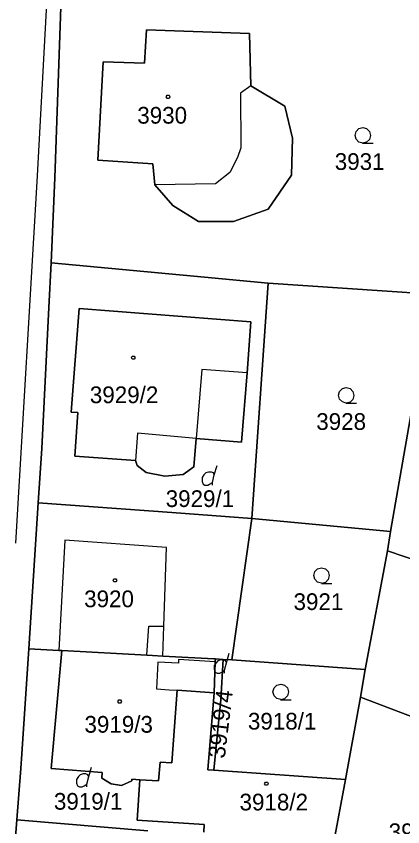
# Model space of a CAD drawing. Extents: x -263587 to -261993, y -1238795 to -1236748.
# Drawn here: x -262927.6 to -262890.6, y -1238078.5 to -1238000.9 of the extents above; entities that cross this region are included whole.
import ezdxf

# ---------------------------------------------------------------- set-up
doc = ezdxf.new("R2010")
doc.units = 0
doc.layers.add('Vrstva 1', color=7, linetype='Continuous')

msp = doc.modelspace()

# ---------------------------------------------------------------- linework, layer by layer
at = {"layer": 'Vrstva 1'}
for p, q in [((-262924.5, -1237996.8), (-262925.57, -1238016.17)), ((-262923.19, -1237996.8), (-262923.88, -1238016.37)), ((-262923.88, -1238016.37), (-262923.19, -1237996.8)), ((-262915.12, -1238002.2), (-262915.29, -1238005.41)), ((-262915.29, -1238005.41), (-262915.12, -1238002.2)), ((-262905.25, -1238002.56), (-262915.12, -1238002.2)), ((-262915.12, -1238002.2), (-262905.25, -1238002.56)), ((-262905.14, -1238007.57), (-262905.25, -1238002.56)), ((-262905.25, -1238002.56), (-262905.14, -1238007.57)), ((-262919.25, -1238005.29), (-262919.76, -1238014.67)), ((-262919.76, -1238014.67), (-262919.25, -1238005.29)), ((-262915.29, -1238005.41), (-262919.25, -1238005.29)), ((-262919.25, -1238005.29), (-262915.29, -1238005.41)), ((-262905.14, -1238007.57), (-262906.13, -1238008.26)), ((-262901.89, -1238009.51), (-262905.14, -1238007.57)), ((-262905.14, -1238007.57), (-262901.89, -1238009.51)), ((-262906.13, -1238008.26), (-262906.11, -1238013.5)), ((-262901.14, -1238012.57), (-262901.89, -1238009.51)), ((-262901.89, -1238009.51), (-262901.14, -1238012.57)), ((-262901.24, -1238016.12), (-262901.14, -1238012.57)), ((-262901.14, -1238012.57), (-262901.24, -1238016.12)), ((-262906.11, -1238013.5), (-262906.41, -1238014.44)), ((-262906.41, -1238014.44), (-262907.15, -1238015.86)), ((-262919.76, -1238014.67), (-262914.51, -1238015.05)), ((-262914.51, -1238015.05), (-262919.76, -1238014.67)), ((-262914.51, -1238015.05), (-262914.33, -1238017.04)), ((-262914.33, -1238017.04), (-262914.51, -1238015.05)), ((-262907.15, -1238015.86), (-262908.52, -1238016.95)), ((-262925.57, -1238016.17), (-262927.63, -1238051.34)), ((-262923.88, -1238016.37), (-262924.22, -1238024.51)), ((-262924.22, -1238024.51), (-262923.88, -1238016.37)), ((-262903.47, -1238019.38), (-262901.24, -1238016.12)), ((-262901.24, -1238016.12), (-262903.47, -1238019.38)), ((-262908.52, -1238016.95), (-262914.33, -1238017.04)), ((-262914.33, -1238017.04), (-262912.6, -1238019.01)), ((-262912.6, -1238019.01), (-262914.33, -1238017.04)), ((-262912.6, -1238019.01), (-262910.15, -1238020.57)), ((-262910.15, -1238020.57), (-262912.6, -1238019.01)), ((-262906.79, -1238020.57), (-262903.47, -1238019.38)), ((-262903.47, -1238019.38), (-262906.79, -1238020.57)), ((-262910.15, -1238020.57), (-262906.79, -1238020.57)), ((-262906.79, -1238020.57), (-262910.15, -1238020.57)), ((-262924.22, -1238024.51), (-262924.44, -1238028.79)), ((-262924.44, -1238028.79), (-262924.22, -1238024.51)), ((-262909.56, -1238025.88), (-262924.22, -1238024.51)), ((-262924.22, -1238024.51), (-262909.56, -1238025.88)), ((-262903.47, -1238026.45), (-262909.56, -1238025.88)), ((-262909.56, -1238025.88), (-262903.47, -1238026.45)), ((-262905.05, -1238048.98), (-262903.47, -1238026.45)), ((-262903.47, -1238026.45), (-262905.05, -1238048.98)), ((-262903.47, -1238026.45), (-262887.93, -1238027.52)), ((-262887.93, -1238027.52), (-262903.47, -1238026.45)), ((-262924.44, -1238028.79), (-262925.12, -1238042.27)), ((-262925.12, -1238042.27), (-262924.44, -1238028.79)), ((-262922.32, -1238038.79), (-262921.56, -1238028.88)), ((-262921.56, -1238028.88), (-262922.32, -1238038.79)), ((-262921.56, -1238028.88), (-262905.13, -1238030.16)), ((-262905.13, -1238030.16), (-262921.56, -1238028.88)), ((-262905.13, -1238030.16), (-262905.49, -1238035.03)), ((-262905.49, -1238035.03), (-262905.13, -1238030.16)), ((-262909.81, -1238034.73), (-262910.37, -1238041.32)), ((-262905.49, -1238035.03), (-262909.81, -1238034.73)), ((-262905.49, -1238035.03), (-262906.03, -1238041.69)), ((-262906.03, -1238041.69), (-262905.49, -1238035.03)), ((-262921.67, -1238038.82), (-262922.32, -1238038.79)), ((-262922.32, -1238038.79), (-262921.67, -1238038.82)), ((-262921.97, -1238043.01), (-262921.67, -1238038.82)), ((-262921.67, -1238038.82), (-262921.97, -1238043.01)), ((-262891.79, -1238050.23), (-262889.81, -1238038.9)), ((-262889.81, -1238038.9), (-262891.79, -1238050.23)), ((-262915.98, -1238040.82), (-262916.15, -1238043.42)), ((-262910.37, -1238041.32), (-262915.98, -1238040.82)), ((-262910.37, -1238041.32), (-262910.59, -1238044.05)), ((-262910.59, -1238044.05), (-262910.37, -1238041.32)), ((-262906.03, -1238041.69), (-262910.37, -1238041.32)), ((-262910.37, -1238041.32), (-262906.03, -1238041.69)), ((-262925.12, -1238042.27), (-262925.48, -1238047.47)), ((-262925.48, -1238047.47), (-262925.12, -1238042.27)), ((-262916.15, -1238043.42), (-262921.97, -1238043.01)), ((-262921.97, -1238043.01), (-262916.15, -1238043.42)), ((-262915.99, -1238043.9), (-262916.15, -1238043.42)), ((-262916.15, -1238043.42), (-262915.99, -1238043.9)), ((-262915.14, -1238044.57), (-262915.99, -1238043.9)), ((-262915.99, -1238043.9), (-262915.14, -1238044.57)), ((-262908.63, -1238044.8), (-262908.36, -1238043.9)), ((-262913.37, -1238044.93), (-262915.14, -1238044.57)), ((-262915.14, -1238044.57), (-262913.37, -1238044.93)), ((-262910.59, -1238044.05), (-262911.61, -1238044.78)), ((-262911.61, -1238044.78), (-262910.59, -1238044.05)), ((-262911.61, -1238044.78), (-262913.37, -1238044.93)), ((-262913.37, -1238044.93), (-262911.61, -1238044.78)), ((-262926.37, -1238061.45), (-262925.48, -1238047.47)), ((-262925.48, -1238047.47), (-262926.37, -1238061.45)), ((-262925.48, -1238047.47), (-262912.7, -1238048.41)), ((-262912.7, -1238048.41), (-262925.48, -1238047.47)), ((-262912.7, -1238048.41), (-262905.05, -1238048.98)), ((-262905.05, -1238048.98), (-262912.7, -1238048.41)), ((-262906.97, -1238062.51), (-262905.05, -1238048.98)), ((-262905.05, -1238048.98), (-262906.97, -1238062.51)), ((-262891.79, -1238050.23), (-262905.05, -1238048.98)), ((-262905.05, -1238048.98), (-262891.79, -1238050.23)), ((-262892.07, -1238052.07), (-262891.79, -1238050.23)), ((-262891.79, -1238050.23), (-262892.07, -1238052.07)), ((-262922.91, -1238051.04), (-262923.48, -1238061.61)), ((-262913.2, -1238051.74), (-262922.91, -1238051.04)), ((-262913.47, -1238059.3), (-262913.2, -1238051.74)), ((-262894.2, -1238063.43), (-262892.07, -1238052.07)), ((-262892.07, -1238052.07), (-262894.2, -1238063.43)), ((-262892.07, -1238052.07), (-262876.57, -1238057.4)), ((-262876.57, -1238057.4), (-262892.07, -1238052.07)), ((-262915.07, -1238062.06), (-262914.9, -1238059.29)), ((-262914.9, -1238059.29), (-262913.47, -1238059.3)), ((-262913.55, -1238062.15), (-262913.47, -1238059.3)), ((-262926.37, -1238061.45), (-262927.02, -1238071.5)), ((-262927.02, -1238071.5), (-262926.37, -1238061.45)), ((-262923.48, -1238061.61), (-262926.37, -1238061.45)), ((-262926.37, -1238061.45), (-262923.48, -1238061.61)), ((-262923.22, -1238061.62), (-262924.23, -1238072.91)), ((-262924.23, -1238072.91), (-262923.22, -1238061.62)), ((-262923.22, -1238061.62), (-262923.48, -1238061.61)), ((-262923.48, -1238061.61), (-262923.22, -1238061.62)), ((-262915.07, -1238062.06), (-262923.22, -1238061.62)), ((-262923.22, -1238061.62), (-262915.07, -1238062.06)), ((-262914.54, -1238062.09), (-262915.07, -1238062.06)), ((-262915.07, -1238062.06), (-262914.54, -1238062.09)), ((-262913.55, -1238062.15), (-262914.54, -1238062.09)), ((-262914.54, -1238062.09), (-262913.55, -1238062.15)), ((-262908.67, -1238062.4), (-262913.55, -1238062.15)), ((-262913.55, -1238062.15), (-262908.67, -1238062.4)), ((-262912.04, -1238062.48), (-262912.06, -1238062.83)), ((-262908.54, -1238062.69), (-262912.04, -1238062.48)), ((-262908.53, -1238062.41), (-262908.67, -1238062.4)), ((-262908.67, -1238062.4), (-262908.53, -1238062.41)), ((-262908.53, -1238062.41), (-262908.54, -1238062.69)), ((-262908.54, -1238062.69), (-262908.53, -1238062.41)), ((-262907.77, -1238062.46), (-262908.53, -1238062.41)), ((-262908.53, -1238062.41), (-262907.77, -1238062.46)), ((-262908.01, -1238066.3), (-262907.77, -1238062.46)), ((-262907.77, -1238062.46), (-262908.01, -1238066.3)), ((-262906.97, -1238062.51), (-262907.77, -1238062.46)), ((-262907.77, -1238062.46), (-262906.97, -1238062.51)), ((-262907.47, -1238062.78), (-262907.2, -1238061.88)), ((-262894.2, -1238063.43), (-262906.97, -1238062.51)), ((-262906.97, -1238062.51), (-262894.2, -1238063.43)), ((-262914.03, -1238062.73), (-262914.17, -1238065.27)), ((-262912.06, -1238062.83), (-262914.03, -1238062.73)), ((-262908.54, -1238062.69), (-262908.65, -1238065.68)), ((-262908.65, -1238065.68), (-262908.54, -1238062.69)), ((-262894.64, -1238066.09), (-262894.2, -1238063.43)), ((-262894.2, -1238063.43), (-262894.64, -1238066.09)), ((-262914.17, -1238065.27), (-262912.96, -1238065.37)), ((-262912.96, -1238065.37), (-262912.19, -1238065.42)), ((-262912.69, -1238072.37), (-262912.19, -1238065.42)), ((-262912.19, -1238065.42), (-262912.69, -1238072.37)), ((-262912.19, -1238065.42), (-262908.65, -1238065.68)), ((-262908.65, -1238065.68), (-262912.19, -1238065.42)), ((-262908.65, -1238065.68), (-262909.26, -1238073.03)), ((-262909.26, -1238073.03), (-262908.65, -1238065.68)), ((-262908.67, -1238073.06), (-262908.01, -1238066.3)), ((-262908.01, -1238066.3), (-262908.67, -1238073.06)), ((-262896.1, -1238073.96), (-262894.64, -1238066.09)), ((-262894.64, -1238066.09), (-262896.1, -1238073.96)), ((-262894.64, -1238066.09), (-262880.22, -1238071.61)), ((-262880.22, -1238071.61), (-262894.64, -1238066.09)), ((-262927.02, -1238071.5), (-262927.11, -1238072.91)), ((-262927.11, -1238072.91), (-262927.02, -1238071.5)), ((-262913.95, -1238074.08), (-262913.82, -1238072.29)), ((-262913.82, -1238072.29), (-262913.95, -1238074.08)), ((-262913.82, -1238072.29), (-262912.69, -1238072.37)), ((-262912.69, -1238072.37), (-262913.82, -1238072.29)), ((-262927.11, -1238072.91), (-262927.5, -1238077.82)), ((-262927.5, -1238077.82), (-262927.11, -1238072.91)), ((-262924.23, -1238072.91), (-262919.35, -1238073.29)), ((-262919.35, -1238073.29), (-262924.23, -1238072.91)), ((-262920.63, -1238073.68), (-262920.36, -1238072.78)), ((-262919.35, -1238073.29), (-262919.39, -1238073.84)), ((-262919.39, -1238073.84), (-262919.35, -1238073.29)), ((-262909.26, -1238073.03), (-262908.67, -1238073.06)), ((-262908.67, -1238073.06), (-262909.26, -1238073.03)), ((-262896.1, -1238073.96), (-262908.67, -1238073.06)), ((-262908.67, -1238073.06), (-262896.1, -1238073.96)), ((-262919.39, -1238073.84), (-262918.48, -1238074.38)), ((-262918.48, -1238074.38), (-262919.39, -1238073.84)), ((-262917.5, -1238074.53), (-262916.51, -1238074.1)), ((-262916.51, -1238074.1), (-262917.5, -1238074.53)), ((-262916.51, -1238074.1), (-262916.5, -1238073.94)), ((-262916.5, -1238073.94), (-262916.51, -1238074.1)), ((-262916.5, -1238073.94), (-262915.74, -1238073.99)), ((-262915.74, -1238073.99), (-262916.5, -1238073.94)), ((-262916.01, -1238077.84), (-262915.74, -1238073.99)), ((-262915.74, -1238073.99), (-262916.01, -1238077.84)), ((-262915.74, -1238073.99), (-262913.95, -1238074.08)), ((-262913.95, -1238074.08), (-262915.74, -1238073.99)), ((-262897.27, -1238080.27), (-262896.1, -1238073.96)), ((-262896.1, -1238073.96), (-262897.27, -1238080.27)), ((-262918.48, -1238074.38), (-262917.5, -1238074.53)), ((-262917.5, -1238074.53), (-262918.48, -1238074.38)), ((-262928.43, -1238089.35), (-262927.5, -1238077.82)), ((-262927.5, -1238077.82), (-262928.43, -1238089.35)), ((-262927.5, -1238077.82), (-262915, -1238078.87)), ((-262915, -1238078.87), (-262927.5, -1238077.82)), ((-262909.6, -1238078.28), (-262916.01, -1238077.84)), ((-262916.01, -1238077.84), (-262909.6, -1238078.28)), ((-262909.64, -1238079), (-262909.6, -1238078.28)), ((-262909.6, -1238078.28), (-262909.64, -1238079))]:
    msp.add_line(p, q, dxfattribs=at)
for points in [[(-262912.96, -1238008.47), (-262912.87, -1238008.62), (-262912.96, -1238008.77), (-262913.14, -1238008.77), (-262913.23, -1238008.62), (-262913.14, -1238008.47)], [(-262916.29, -1238033.44), (-262916.2, -1238033.59), (-262916.29, -1238033.74), (-262916.47, -1238033.74), (-262916.56, -1238033.59), (-262916.47, -1238033.44)], [(-262918.04, -1238054.75), (-262917.95, -1238054.9), (-262918.04, -1238055.05), (-262918.22, -1238055.05), (-262918.31, -1238054.9), (-262918.22, -1238054.75)], [(-262917.59, -1238066.35), (-262917.5, -1238066.5), (-262917.59, -1238066.65), (-262917.77, -1238066.65), (-262917.86, -1238066.5), (-262917.77, -1238066.35)], [(-262903.56, -1238074.21), (-262903.47, -1238074.36), (-262903.56, -1238074.51), (-262903.74, -1238074.51), (-262903.83, -1238074.36), (-262903.74, -1238074.21)]]:
    msp.add_lwpolyline(points, close=True, dxfattribs=at)
for points in [[(-262894.43, -1238013.05), (-262894.81, -1238012.95), (-262895.08, -1238012.68), (-262895.18, -1238012.31), (-262895.08, -1238011.94), (-262894.81, -1238011.67), (-262894.44, -1238011.57), (-262894.07, -1238011.67), (-262893.8, -1238011.94), (-262893.7, -1238012.32), (-262893.8, -1238012.7), (-262894.07, -1238012.97), (-262894.45, -1238013.07), (-262893.45, -1238013.07)], [(-262896.01, -1238037.93), (-262896.39, -1238037.83), (-262896.66, -1238037.56), (-262896.76, -1238037.19), (-262896.66, -1238036.82), (-262896.39, -1238036.55), (-262896.02, -1238036.45), (-262895.65, -1238036.55), (-262895.38, -1238036.82), (-262895.28, -1238037.2), (-262895.38, -1238037.58), (-262895.65, -1238037.85), (-262896.03, -1238037.95), (-262895.03, -1238037.95)], [(-262908.81, -1238045.79), (-262908.81, -1238045.52), (-262908.63, -1238044.8), (-262908.72, -1238044.62), (-262908.9, -1238044.53), (-262909.17, -1238044.53), (-262909.44, -1238044.62), (-262909.62, -1238044.8), (-262909.8, -1238045.07), (-262909.8, -1238045.43), (-262909.71, -1238045.7), (-262909.53, -1238045.79), (-262909.26, -1238045.79), (-262909.08, -1238045.7), (-262908.81, -1238045.52)], [(-262898.37, -1238055.17), (-262898.75, -1238055.07), (-262899.02, -1238054.8), (-262899.12, -1238054.43), (-262899.02, -1238054.06), (-262898.75, -1238053.79), (-262898.38, -1238053.69), (-262898.01, -1238053.79), (-262897.74, -1238054.06), (-262897.64, -1238054.44), (-262897.74, -1238054.82), (-262898.01, -1238055.09), (-262898.39, -1238055.19), (-262897.39, -1238055.19)], [(-262907.65, -1238063.77), (-262907.65, -1238063.5), (-262907.47, -1238062.78), (-262907.56, -1238062.6), (-262907.74, -1238062.51), (-262908.01, -1238062.51), (-262908.28, -1238062.6), (-262908.46, -1238062.78), (-262908.64, -1238063.05), (-262908.64, -1238063.41), (-262908.55, -1238063.68), (-262908.37, -1238063.77), (-262908.1, -1238063.77), (-262907.92, -1238063.68), (-262907.65, -1238063.5)], [(-262902.27, -1238066.31), (-262902.65, -1238066.21), (-262902.92, -1238065.94), (-262903.02, -1238065.57), (-262902.92, -1238065.2), (-262902.65, -1238064.93), (-262902.28, -1238064.83), (-262901.91, -1238064.93), (-262901.64, -1238065.2), (-262901.54, -1238065.58), (-262901.64, -1238065.96), (-262901.91, -1238066.23), (-262902.29, -1238066.33), (-262901.29, -1238066.33)], [(-262920.81, -1238074.67), (-262920.81, -1238074.4), (-262920.63, -1238073.68), (-262920.72, -1238073.5), (-262920.9, -1238073.41), (-262921.17, -1238073.41), (-262921.44, -1238073.5), (-262921.62, -1238073.68), (-262921.8, -1238073.95), (-262921.8, -1238074.31), (-262921.71, -1238074.58), (-262921.53, -1238074.67), (-262921.26, -1238074.67), (-262921.08, -1238074.58), (-262920.81, -1238074.4)]]:
    msp.add_lwpolyline(points, dxfattribs=at)

# ---------------------------------------------------------------- texts
for s, p in [('3930', (-262915.993, -1238011.19)), ('3931', (-262897.115, -1238015.62)), ('3929/2', (-262920.526, -1238037.94)), ('3928', (-262898.884, -1238040.5)), ('3929/1', (-262913.277, -1238047.88)), ('3920', (-262921.073, -1238057.47)), ('3921', (-262901.055, -1238057.74)), ('3919/3', (-262921.042, -1238069.48)), ('3918/1', (-262905.417, -1238069.18)), ('3919/1', (-262923.963, -1238076.85)), ('3918/2', (-262906.216, -1238076.92)), ('3917', (-262891.96, -1238079.76))]:
    msp.add_text(s, height=1.6, dxfattribs=at).set_placement(p)
msp.add_text('3919/4', height=1.6, rotation=83.07888, dxfattribs=at).set_placement((-262907.634, -1238071.998))

doc.saveas('drawing.dxf')
